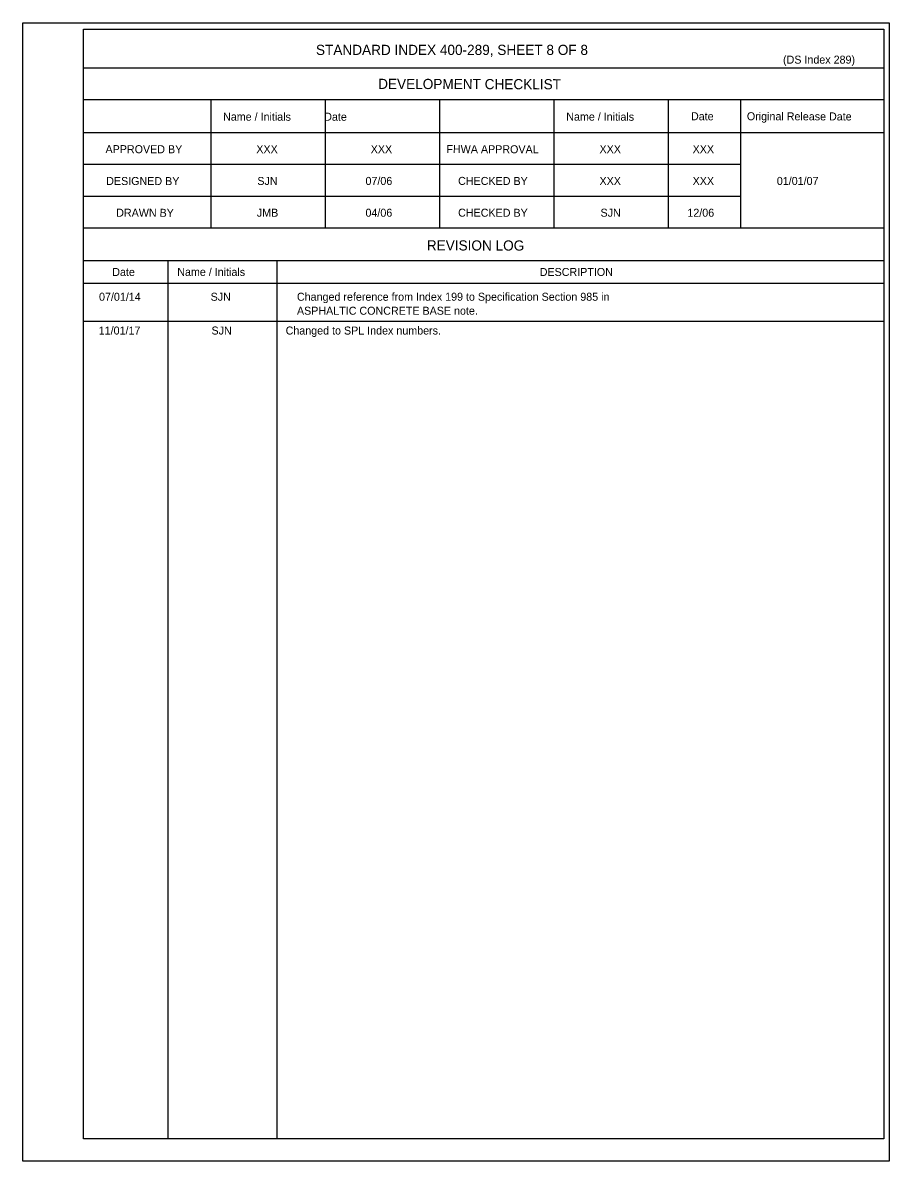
# Model space of a CAD drawing. Extents: x 1.4 to 54.1, y -0.5 to 22.6.
# Drawn here: x 37.73 to 54.09, y -0.48 to 21.02 of the extents above; entities that cross this region are included whole.
import ezdxf

# ---------------------------------------------------------------- set-up
doc = ezdxf.new("R2010")
doc.units = 0
for name, color, linetype in [('AdhocPoint_dp', 7, 'Continuous'), ('Patterning', 7, 'Continuous'), ('PlotBorder_dp', 7, 'Continuous'), ('TextMisc', 7, 'Continuous')]:
    doc.layers.add(name, color=color, linetype=linetype)

msp = doc.modelspace()

# ---------------------------------------------------------------- linework, layer by layer
at = {"layer": 'Patterning'}
msp.add_line((37.733, -0.477), (37.733, -0.477), dxfattribs=at)
msp.add_lwpolyline([(37.733, 21.023), (54.093, 21.023), (54.093, -0.477), (37.733, -0.477)], close=True, dxfattribs=at)
at = {"layer": 'PlotBorder_dp'}
msp.add_line((38.881, 15.389), (53.991, 15.389), dxfattribs=at)
at = {"layer": 'TextMisc'}
for p, q in [((53.991, 20.165), (38.881, 20.165)), ((53.991, 19.565), (38.881, 19.565)), ((41.281, 19.565), (41.281, 17.145)), ((43.441, 19.565), (43.441, 17.145)), ((45.601, 19.565), (45.601, 17.145)), ((47.761, 19.565), (47.761, 17.145)), ((49.921, 19.565), (49.921, 17.145)), ((51.282, 19.565), (51.282, 17.145)), ((53.991, 18.945), (38.881, 18.945)), ((51.282, 18.345), (38.881, 18.345)), ((51.282, 17.745), (38.881, 17.745)), ((53.991, 17.145), (38.881, 17.145)), ((53.991, 16.524), (38.881, 16.524)), ((40.471, 16.524), (40.471, -0.056)), ((42.528, 16.524), (42.528, -0.056)), ((53.991, 16.101), (38.881, 16.101))]:
    msp.add_line(p, q, dxfattribs=at)
msp.add_lwpolyline([(38.881, 20.901), (53.991, 20.901), (53.991, -0.056), (38.881, -0.056)], close=True, dxfattribs=at)

# ---------------------------------------------------------------- texts
at = {"layer": 'AdhocPoint_dp'}
for s, height, p in [('STANDARD INDEX 400-289, SHEET 8 OF 8', 0.192, (43.269, 20.415)), ('XXX', 0.1512, (42.143, 18.56)), ('XXX', 0.1512, (44.303, 18.56)), ('XXX', 0.1512, (48.623, 18.56)), ('XXX', 0.1512, (50.381, 18.56)), ('SJN', 0.1512, (42.162, 17.96)), ('07/06', 0.1512, (44.204, 17.96)), ('XXX', 0.1512, (48.623, 17.96)), ('XXX', 0.1512, (50.381, 17.96)), ('01/01/07', 0.1512, (51.971, 17.96)), ('JMB', 0.1512, (42.153, 17.36)), ('04/06', 0.1512, (44.204, 17.36)), ('SJN', 0.1512, (48.642, 17.36)), ('12/06', 0.1512, (50.282, 17.36)), ('DESCRIPTION', 0.1512, (47.494, 16.241)), ('07/01/14', 0.1512, (39.173, 15.773)), ('SJN', 0.1512, (41.28, 15.773)), ('Changed reference from Index 199 to Specification Section 985 in ', 0.1512, (42.91, 15.773)), ('ASPHALTIC CONCRETE BASE note. ', 0.1512, (42.91, 15.509)), ('11/01/17', 0.1512, (39.167, 15.135)), ('SJN', 0.1512, (41.297, 15.135)), ('Changed to SPL Index numbers.', 0.1512, (42.696, 15.135))]:
    msp.add_text(s, height=height, dxfattribs=at).set_placement(p)
for s, height, p in [('DEVELOPMENT CHECKLIST', 0.192, (44.443, 19.773)), ('Name / Initials', 0.1512, (41.515, 19.175)), ('Date', 0.1512, (43.425, 19.173)), ('Name / Initials', 0.1512, (47.995, 19.175)), ('Date', 0.1512, (50.35, 19.182)), ('Original Release Date', 0.1512, (51.405, 19.182)), ('APPROVED BY', 0.1512, (39.295, 18.561)), ('FHWA APPROVAL', 0.1512, (45.732, 18.561)), ('DESIGNED BY', 0.1512, (39.308, 17.96)), ('CHECKED BY', 0.1512, (45.953, 17.961)), ('DRAWN BY', 0.1512, (39.497, 17.36)), ('CHECKED BY', 0.1512, (45.953, 17.361)), ('REVISION LOG', 0.192, (45.362, 16.724)), ('Date', 0.1512, (39.423, 16.241)), ('Name / Initials', 0.1512, (40.65, 16.243))]:
    msp.add_text(s, height=height, rotation=359.8756, dxfattribs=at).set_placement(p)
at = {"layer": 'PlotBorder_dp'}
msp.add_text('(DS Index 289)', height=0.1512, dxfattribs=at).set_placement((52.088, 20.251))

doc.saveas('drawing.dxf')
